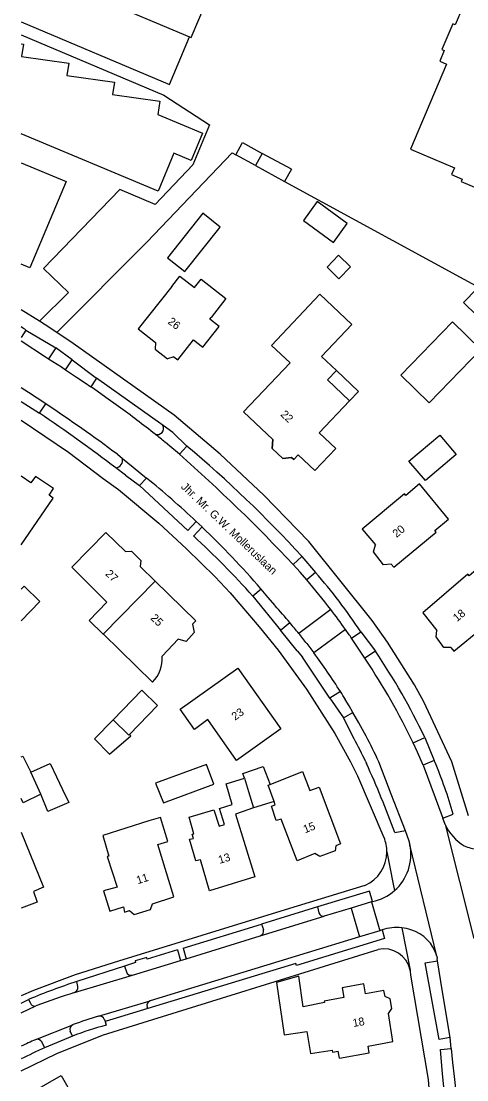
# Model space of a CAD drawing. Extents: x 194485 to 197793, y 468269 to 470822.
# Drawn here: x 194485.4 to 194552.2, y 470202.3 to 470361 of the extents above; entities that cross this region are included whole.
import ezdxf

# ---------------------------------------------------------------- set-up
doc = ezdxf.new("R2010")
doc.units = 0
for name, color, linetype in [('BGT grensvlak gebouwinstallatie plus 1', 7, 'Continuous'), ('BGT grensvlak onbegroeid terreindeel', 7, 'Continuous'), ('BGT grensvlak overig bouwwerk', 7, 'Continuous'), ('BGT grensvlak pand op maaiveld', 7, 'Continuous'), ('BGT grensvlak pand op maaiveld LR', 7, 'Continuous'), ('BGT grensvlak wegdeel', 7, 'Continuous'), ('BGT tekst huisnummerreeks', 7, 'Continuous'), ('BGT tekst openbare ruimte label weg', 7, 'Continuous'), ('GEM grensvlak beperking object', 7, 'Continuous')]:
    doc.layers.add(name, color=color, linetype=linetype)

msp = doc.modelspace()

# ---------------------------------------------------------------- linework, layer by layer
at = {"layer": 'BGT grensvlak gebouwinstallatie plus 1'}
msp.add_line((194520.54, 470339.4), (194517.6, 470341), dxfattribs=at)
for points in [[(194517.6, 470341), (194518.6, 470342.84), (194521.54, 470341.21)], [(194527.74, 470331.17), (194532.24, 470327.87), (194534.3, 470330.7), (194529.8, 470333.99), (194527.74, 470331.17)], [(194558.86, 470318.1), (194553.75, 470320.91), (194551.74, 470318.83), (194555.79, 470314.92)], [(194532.69, 470308.64), (194535.99, 470305.5), (194534.66, 470304.11)], [(194499.19, 470256.28), (194496.43, 470253.44), (194498.66, 470251.12), (194501.85, 470253.88), (194501.65, 470254.07)]]:
    msp.add_lwpolyline(points, dxfattribs=at)
at = {"layer": 'BGT grensvlak onbegroeid terreindeel'}
for points in [[(194485.41, 470360.93), (194507.65, 470351.54), (194510.67, 470358.68)], [(194485.41, 470358.98), (194506.79, 470349.95), (194513.67, 470345.49), (194511.17, 470339.51), (194505.51, 470333.57), (194500.21, 470335.79), (194488.75, 470323.97), (194492.49, 470320.35), (194488.18, 470316.04)], [(194485.41, 470339.81), (194492.14, 470336.99), (194486.73, 470324.06), (194485.41, 470324.62)], [(194490.75, 470314.36), (194504.26, 470327.9), (194517.03, 470341.31), (194517.6, 470341)], [(194524.92, 470336.98), (194557.37, 470319.3), (194558.33, 470321.04)]]:
    msp.add_lwpolyline(points, dxfattribs=at)
at = {"layer": 'BGT grensvlak overig bouwwerk'}
msp.add_lwpolyline([(194550.07, 470315.94), (194542.33, 470307.97), (194546.6, 470303.83), (194554.34, 470311.79), (194550.07, 470315.94)], dxfattribs=at)
at = {"layer": 'BGT grensvlak pand op maaiveld'}
for p, q in [((194486.27, 470368.98), (194510.67, 470358.68)), ((194521.54, 470341.21), (194520.54, 470339.4)), ((194525.93, 470338.83), (194521.54, 470341.21)), ((194520.54, 470339.4), (194524.92, 470336.98)), ((194525.93, 470338.83), (194524.92, 470336.98)), ((194507.99, 470321.24), (194509.22, 470322.82)), ((194509.22, 470322.82), (194511.41, 470321.1)), ((194511.41, 470321.1), (194512.39, 470322.36)), ((194512.39, 470322.36), (194516.12, 470319.45)), ((194507.99, 470321.24), (194502.94, 470314.89)), ((194516.12, 470319.45), (194513.91, 470316.61)), ((194502.94, 470314.89), (194505.54, 470312.86)), ((194505.54, 470312.86), (194505.49, 470311.88)), ((194505.49, 470311.88), (194507.34, 470310.43)), ((194508.28, 470310.72), (194507.34, 470310.43)), ((194497.72, 470269.14), (194497.75, 470269.12)), ((194497.75, 470269.12), (194505.12, 470261.91)), ((194518.66, 470248.25), (194521.7, 470249.29)), ((194521.7, 470249.29), (194522.77, 470246.6)), ((194490.73, 470247.72), (194491.63, 470245.82)), ((194518.88, 470247.54), (194518.66, 470248.25)), ((194523.33, 470244.02), (194520.27, 470243.06)), ((194533.15, 470205.55), (194532.97, 470206.58))]:
    msp.add_line(p, q, dxfattribs=at)
for points in [[(194510.67, 470358.68), (194510.9, 470358.59), (194514.35, 470366.76)], [(194551.64, 470363.2), (194550.49, 470360.49), (194550.12, 470360.65), (194548.48, 470356.78), (194548.86, 470356.62), (194548.18, 470355.02), (194549.19, 470354.59), (194543.8, 470341.87), (194550.39, 470339.05), (194549.96, 470338.04), (194551.56, 470337.35), (194551.4, 470336.98), (194555.27, 470335.34), (194555.43, 470335.72), (194558.14, 470334.57), (194557.98, 470334.19), (194561.85, 470332.55), (194562.01, 470332.93), (194563.6, 470332.25)], [(194485.41, 470357.66), (194485.75, 470357.61), (194485.48, 470355.74), (194492.55, 470354.76), (194492.28, 470352.89), (194499.39, 470351.89), (194499.12, 470350.03), (194506.2, 470349.04), (194505.92, 470347.06), (194512.61, 470344.25), (194510.9, 470340.17), (194508.3, 470341.23), (194505.94, 470335.55), (194485.41, 470344.15)], [(194507.36, 470325.57), (194509.94, 470323.51), (194515.25, 470330.17), (194512.67, 470332.23), (194507.36, 470325.57)], [(194533.02, 470325.93), (194531.28, 470324.14), (194533.07, 470322.4), (194534.81, 470324.19), (194533.02, 470325.93)], [(194532.69, 470308.64), (194530.43, 470310.78), (194534.98, 470315.57), (194530.21, 470320.08), (194522.96, 470312.42), (194525.73, 470309.79), (194518.75, 470302.48), (194523.14, 470298.29)], [(194508.28, 470310.72), (194508.88, 470310.25), (194511.27, 470313.27), (194512.65, 470312.18), (194515.09, 470315.27), (194513.71, 470316.37), (194513.91, 470316.61)], [(194532.69, 470308.64), (194531.36, 470307.24), (194534.66, 470304.11)], [(194534.66, 470304.11), (194530.11, 470299.33), (194532.6, 470296.96), (194529.43, 470293.64), (194526.95, 470296), (194526.28, 470295.3), (194525.96, 470295.6)], [(194546.02, 470292.16), (194543.56, 470295.07), (194548.17, 470298.95), (194550.62, 470296.04), (194546.02, 470292.16)], [(194525.96, 470295.6), (194524.64, 470295.46), (194523.85, 470296.21), (194523.06, 470296.97), (194523.14, 470298.29)], [(194485.41, 470282.52), (194490.21, 470289.49), (194489.6, 470289.95), (194490.27, 470290.98), (194487.57, 470292.78), (194486.86, 470291.81), (194485.41, 470292.8)], [(194540.91, 470279.62), (194541.31, 470279.15), (194547.65, 470284.42), (194547.44, 470284.67), (194549.49, 470286.38), (194545.15, 470291.64), (194543.1, 470289.93), (194542.89, 470290.17), (194536.56, 470284.89), (194538.53, 470282.51)], [(194498.28, 470273.9), (194493.01, 470279.15), (194498.1, 470284.38)], [(194498.1, 470284.38), (194501.06, 470281.53), (194501.97, 470281.55), (194503.35, 470280.18), (194503.26, 470279.29), (194505.53, 470277.08)], [(194540.91, 470279.62), (194539.76, 470279.53), (194538.24, 470281.47), (194538.53, 470282.51)], [(194549.82, 470267.14), (194550.3, 470266.55), (194554.46, 470269.95), (194555.5, 470269.47), (194557.04, 470270.73), (194556.78, 470271.84), (194557.24, 470272.22), (194557.04, 470272.47), (194559.75, 470274.69), (194555.26, 470280.13), (194552.61, 470277.85), (194552.39, 470278.1), (194545.63, 470272.31), (194547.76, 470269.68)], [(194485.41, 470275.87), (194485.86, 470276.33), (194488.2, 470274.02), (194485.41, 470271.14)], [(194505.53, 470277.08), (194511.62, 470271.14), (194511.1, 470270.6), (194511.35, 470269.36), (194510.17, 470268.04), (194508.96, 470268.36), (194506.56, 470265.81)], [(194498.28, 470273.9), (194495.62, 470271.18), (194497.72, 470269.14)], [(194549.82, 470267.14), (194548.78, 470267.12), (194547.62, 470268.72), (194547.76, 470269.68)], [(194517.69, 470250.2), (194513.38, 470256.32), (194511.38, 470254.82), (194509.24, 470257.88), (194517.89, 470264.02), (194524.36, 470254.92), (194517.69, 470250.2)], [(194501.65, 470254.07), (194505.87, 470258.43), (194503.49, 470260.73), (194499.19, 470256.28)], [(194499.19, 470256.28), (194501.56, 470253.98), (194501.65, 470254.07)], [(194485.41, 470250.71), (194485.67, 470250.83), (194486.86, 470248.41)], [(194486.86, 470248.41), (194489.76, 470249.74), (194490.73, 470247.72)], [(194514.31, 470246.63), (194513.19, 470249.58), (194505.58, 470246.77), (194506.74, 470243.83), (194514.31, 470246.63)], [(194522.77, 470246.6), (194527.58, 470248.52), (194528.72, 470245.66), (194530.12, 470246.16), (194533.31, 470237.68)], [(194520.27, 470243.06), (194517.57, 470242.12), (194520.43, 470232.72), (194513.64, 470230.64), (194512.28, 470235.3), (194511.61, 470235.13), (194510.64, 470238.36), (194511.27, 470238.49), (194511.04, 470239.15), (194511.3, 470239.2), (194510.58, 470241.67), (194514.3, 470242.78), (194515.12, 470240.34), (194515.89, 470240.59), (194515.16, 470242.99), (194517.07, 470243.59), (194516.16, 470246.67), (194518.88, 470247.54)], [(194488.37, 470245.15), (194485.71, 470243.84), (194485.41, 470244.48)], [(194491.63, 470245.82), (194492.54, 470243.86), (194489.43, 470242.55), (194488.37, 470245.15)], [(194533.31, 470237.68), (194532.62, 470237.36), (194532.48, 470236.61), (194530.2, 470235.77), (194529.45, 470236.24), (194526.8, 470235.14), (194524.42, 470241.39), (194523.66, 470241.17), (194522.95, 470243.34), (194523.51, 470243.53), (194523.33, 470244.02)], [(194505.92, 470237.6), (194507.4, 470238.04), (194506.33, 470241.64), (194504.54, 470241.12)], [(194504.54, 470241.12), (194497.64, 470238.94), (194498.57, 470235.85), (194498.31, 470235.78), (194499.81, 470231.16), (194497.76, 470230.63), (194498.73, 470227.6), (194500.74, 470228.22), (194500.93, 470227.44), (194501.64, 470227.66), (194502.35, 470227.09), (194504.83, 470227.83), (194505.09, 470228.67), (194508.28, 470229.75), (194505.92, 470237.6)], [(194485.41, 470239.44), (194488.74, 470231.16), (194487.24, 470230.53), (194487.82, 470228.91), (194485.41, 470228.02)], [(194527.68, 470213.23), (194527.04, 470217.83), (194523.71, 470216.89), (194524.83, 470209.05), (194528.27, 470209.54)], [(194537.43, 470207.36), (194541.13, 470208.02), (194540.49, 470212.26), (194541.02, 470212.99), (194540.77, 470214.46), (194540, 470214.8), (194539.78, 470215.69), (194537.06, 470215.21), (194536.8, 470216.67), (194533.55, 470216.1), (194533.81, 470214.64), (194530.84, 470214.11), (194530.92, 470213.88), (194527.68, 470213.23)], [(194528.27, 470209.54), (194528.8, 470206.22), (194532.07, 470206.74), (194532.12, 470206.43), (194532.97, 470206.58)], [(194533.15, 470205.55), (194537.61, 470206.33), (194537.43, 470207.36)], [(194485.41, 470199.49), (194491.4, 470202.92), (194494.46, 470197.58), (194495.57, 470198.23), (194498.08, 470193.97), (194496.69, 470193.16)]]:
    msp.add_lwpolyline(points, dxfattribs=at)
msp.add_arc((194501.47, 470265.48), 5.11, 315.6191, 3.6495, dxfattribs=at)
at = {"layer": 'BGT grensvlak pand op maaiveld LR'}
for p, q in [((194497.72, 470269.14), (194505.53, 470277.08)), ((194488.37, 470245.15), (194486.86, 470248.41)), ((194518.88, 470247.54), (194519.5, 470245.55)), ((194522.43, 470246.46), (194522.77, 470246.6)), ((194523.33, 470244.02), (194522.43, 470246.46)), ((194519.5, 470245.55), (194520.27, 470243.06))]:
    msp.add_line(p, q, dxfattribs=at)
at = {"layer": 'BGT grensvlak wegdeel'}
for p, q in [((194488.18, 470316.04), (194485.41, 470317.76)), ((194486.13, 470314.72), (194485.41, 470313.6)), ((194486.13, 470314.72), (194490.6, 470312.05)), ((194490.6, 470312.05), (194489.53, 470310.42)), ((194493.07, 470310.27), (194490.6, 470312.05)), ((194492.07, 470308.78), (194493.07, 470310.27)), ((194493.07, 470310.27), (194496.7, 470307.51)), ((194496.7, 470307.51), (194495.86, 470306.22)), ((194506.68, 470300.42), (194496.7, 470307.51)), ((194485.41, 470304.03), (194488.16, 470302.26)), ((194488.16, 470302.26), (194489.09, 470303.65)), ((194508.14, 470299.38), (194506.68, 470300.42)), ((194508.14, 470299.38), (194510.25, 470297.33)), ((194510.25, 470297.33), (194509.14, 470296.09)), ((194499.84, 470296.1), (194500.59, 470295.48)), ((194500.59, 470295.48), (194502.21, 470294.15)), ((194501.07, 470292.94), (194499.62, 470294.04)), ((194502.21, 470294.15), (194504.2, 470292.52)), ((194501.07, 470292.94), (194503.17, 470291.39)), ((194503.17, 470291.39), (194504.2, 470292.52)), ((194511.66, 470286.02), (194512.53, 470285.19)), ((194511.24, 470283.84), (194512.53, 470285.19)), ((194526.19, 470279.55), (194527.52, 470280.78)), ((194527.52, 470280.78), (194529.54, 470278.38)), ((194529.54, 470278.38), (194528.24, 470277.26)), ((194521.38, 470275.89), (194520.14, 470274.83)), ((194520.14, 470274.83), (194524.3, 470269.74)), ((194531.84, 470272.82), (194527.04, 470269.23)), ((194524.3, 470269.74), (194525.7, 470270.85)), ((194526.82, 470266.6), (194524.3, 470269.74)), ((194534.04, 470269.84), (194529.3, 470266.3)), ((194534.95, 470268.52), (194536.35, 470269.47)), ((194536.35, 470269.47), (194538.53, 470266.58)), ((194528.25, 470267.7), (194529.3, 470266.3)), ((194526.82, 470266.6), (194527.61, 470265.67)), ((194531.68, 470259.51), (194527.61, 470265.67)), ((194538.53, 470266.58), (194536.94, 470265.5)), ((194537.03, 470265.36), (194536.94, 470265.5)), ((194533.29, 470260.5), (194531.68, 470259.51)), ((194531.68, 470259.51), (194533.77, 470256.57)), ((194533.77, 470256.57), (194535.17, 470257.39)), ((194535.35, 470253.45), (194533.77, 470256.57)), ((194544.2, 470252.81), (194545.93, 470253.64)), ((194545.93, 470253.64), (194547.34, 470250.2)), ((194537.1, 470250), (194537.2, 470249.72)), ((194547.34, 470250.2), (194545.71, 470249.49)), ((194545.71, 470249.49), (194548.63, 470241.54)), ((194547.43, 470250), (194547.34, 470250.2)), ((194548.63, 470241.54), (194550.21, 470242.12)), ((194548.98, 470240.56), (194548.63, 470241.54)), ((194548.98, 470240.56), (194553.3, 470223.49)), ((194543.03, 470239.65), (194541.45, 470239.35)), ((194543.59, 470238.09), (194543.03, 470239.65)), ((194547.72, 470220.82), (194543.72, 470237.54)), ((194540.24, 470236.48), (194541.21, 470231.61)), ((194541.21, 470231.61), (194541.39, 470230.67)), ((194537.93, 470228.97), (194534.91, 470228.05)), ((194538.11, 470229.02), (194537.93, 470228.97)), ((194537.93, 470228.97), (194539.18, 470224.65)), ((194529.84, 470228.22), (194521.47, 470225.65)), ((194529.84, 470228.22), (194530.07, 470227.34)), ((194534.91, 470228.05), (194530.86, 470226.82)), ((194534.91, 470228.05), (194536.16, 470223.73)), ((194509.71, 470222.04), (194521.47, 470225.65)), ((194521.27, 470223.89), (194530.86, 470226.82)), ((194521.47, 470225.65), (194521.74, 470224.82)), ((194510.15, 470220.46), (194521.27, 470223.89)), ((194539.18, 470224.65), (194536.16, 470223.73)), ((194539.55, 470224.76), (194539.18, 470224.65)), ((194542.49, 470225.1), (194543.75, 470218.76)), ((194536.16, 470223.73), (194504.74, 470214.14)), ((194508.85, 470221.77), (194509.29, 470220.2)), ((194509.71, 470222.04), (194510.15, 470220.46)), ((194547.72, 470220.82), (194547.8, 470220.49)), ((194500.92, 470219.33), (194493.75, 470217.02)), ((194500.92, 470219.33), (194501.19, 470218.51)), ((194502.12, 470217.99), (194509.29, 470220.2)), ((194509.29, 470220.2), (194510.15, 470220.46)), ((194547.86, 470220.13), (194547.8, 470220.49)), ((194493.41, 470215.38), (194502.12, 470217.99)), ((194493.9, 470216.29), (194493.75, 470217.02)), ((194485.41, 470213.81), (194486.53, 470214.33)), ((194485.41, 470212.32), (194487.62, 470213.38)), ((194486.53, 470214.33), (194486.81, 470213.81)), ((194487.76, 470213.44), (194487.62, 470213.38)), ((194497, 470211.83), (194504.74, 470214.14)), ((194504.4, 470212.98), (194497.99, 470211.06)), ((194504.4, 470212.98), (194504.31, 470213.26)), ((194497.91, 470211.32), (194497.99, 470211.06)), ((194487.59, 470208.32), (194493.14, 470210.54)), ((194493.12, 470208.86), (194492.76, 470209.59)), ((194493.21, 470210.57), (194493.14, 470210.54)), ((194497.99, 470211.06), (194498.15, 470210.49)), ((194487.59, 470208.32), (194487.55, 470208.31)), ((194493.12, 470208.86), (194488.89, 470207.08)), ((194549.89, 470206.99), (194549.74, 470208.62)), ((194488.53, 470207.93), (194488.89, 470207.08))]:
    msp.add_line(p, q, dxfattribs=at)
for points in [[(194490.75, 470314.36), (194489.02, 470315.51), (194488.18, 470316.04)], [(194552.5, 470241.9), (194549.98, 470250), (194545.77, 470258.98), (194544.42, 470261.5), (194540.37, 470267.9), (194538.06, 470271.19), (194528.56, 470283.04), (194521.79, 470289.95), (194515.24, 470296.12), (194508.37, 470301.96), (194493.23, 470312.72), (194490.75, 470314.36)], [(194485.41, 470313.12), (194489.08, 470310.7), (194489.53, 470310.42)], [(194489.53, 470310.42), (194491.44, 470309.19), (194492.07, 470308.78)], [(194492.07, 470308.78), (194493.73, 470307.68), (194494.99, 470306.82), (194495.86, 470306.22)], [(194489.09, 470303.65), (194486.52, 470305.34), (194485.41, 470306.05)], [(194500, 470303.28), (194498.13, 470304.63), (194496.24, 470305.96), (194495.86, 470306.22)], [(194485.41, 470301.19), (194492.5, 470296.42), (194497.72, 470292.47), (194500, 470290.79), (194506.06, 470285.74), (194510.2, 470281.91), (194514.52, 470277.71), (194516.76, 470275.3), (194521.1, 470270.2), (194523.93, 470266.7), (194528.21, 470260.88), (194532.45, 470254.21), (194534.79, 470250), (194535.86, 470247.89), (194539.82, 470238.61)], [(194509.14, 470296.09), (194507.72, 470297.33), (194506.98, 470297.93)], [(194503.17, 470291.39), (194510.4, 470284.67), (194511.66, 470286.02)], [(194528.24, 470277.26), (194527.23, 470278.41), (194526.19, 470279.55)], [(194523.48, 470273.4), (194522.41, 470274.68), (194521.38, 470275.89)], [(194536.94, 470265.5), (194535.96, 470267.02), (194534.95, 470268.52)], [(194535.17, 470257.39), (194534.61, 470258.35), (194534.02, 470259.31)], [(194536.9, 470254.28), (194536.05, 470255.84), (194535.17, 470257.39)], [(194545.71, 470249.49), (194544.86, 470251.41), (194544.2, 470252.81)], [(194543.03, 470239.65), (194540.88, 470245.11), (194539.04, 470250), (194538.81, 470250.49)], [(194536.96, 470231.42), (194525.02, 470227.76), (194500, 470220.11), (194493.52, 470218.05), (194487.28, 470215.68), (194485.41, 470214.88)], [(194538.11, 470229.02), (194537.65, 470230.57), (194529.84, 470228.22)], [(194539.55, 470224.76), (194539.9, 470223.47), (194526.69, 470219.46), (194526.61, 470219.74), (194504.4, 470212.98)], [(194485.41, 470203.66), (194490.77, 470206.25), (194497.61, 470208.97), (194500, 470209.74), (194538.94, 470221.84)], [(194508.85, 470221.77), (194504.3, 470220.38), (194504.24, 470220.65), (194502.49, 470220.14), (194502.55, 470219.87), (194500.92, 470219.33)], [(194549.74, 470208.62), (194548.08, 470208.36), (194545.99, 470219.84), (194547.86, 470220.13)], [(194549.74, 470208.62), (194548.59, 470215.49), (194547.86, 470220.13)], [(194538.71, 470115.06), (194541.76, 470132.92), (194544.49, 470148.78), (194546.12, 470161.52), (194547.24, 470174.3), (194547.43, 470181.27), (194547.35, 470188.24), (194547.04, 470195.29), (194546.51, 470202.32), (194543.84, 470218.01)], [(194550.93, 470197.44), (194549.18, 470197.23), (194548.61, 470203.2), (194548.29, 470206.84), (194549.89, 470206.99)], [(194549.89, 470206.99), (194550.09, 470204.88), (194550.32, 470202.78), (194550.93, 470197.44)]]:
    msp.add_lwpolyline(points, dxfattribs=at)
for centre, radius, start, end in [((194390.43, 470166.64), 176.31, 57.1283, 57.4052), ((194348.17, 470091.58), 254.62, 53.4393, 56.3959), ((194386.53, 470147.95), 192.36, 51.7873, 53.851), ((194337.32, 470079.91), 268.69, 52.8396, 55.8481), ((194505.8, 470300.01), 0.967, 253.1274, 24.9588), ((194387.71, 470149.44), 190.46, 51.2291, 51.7883), ((194391.46, 470156.07), 184.57, 42.5058, 49.9368), ((194499.42, 470295.22), 1.2, 279.911, 12.7454), ((194346.1, 470110.87), 246.76, 43.126, 48.6443), ((194419.29, 470187.57), 135, 46.8238, 51.0254), ((194419.36, 470187.72), 134.84, 40.8389, 46.2944), ((194432.15, 470196.84), 117.58, 41.5502, 47.7271), ((194468.53, 470224.65), 81.29, 33.4624, 41.3746), ((194454.11, 470213.34), 97.88, 37.422, 40.7706), ((194452.62, 470209.26), 95.57, 40.1211, 42.1454), ((194453.93, 470213.2), 98.1, 35.2589, 37.4233), ((194449.88, 470207.04), 99.1, 38.8666, 40.0808), ((194456.95, 470212.65), 90.08, 37.6718, 38.9158), ((194466.61, 470221.96), 82.69, 34.2636, 35.3752), ((194453.18, 470209.78), 94.82, 32.3375, 36.5915), ((194455.7, 470210.5), 98.1, 25.5518, 34), ((194456.34, 470210.93), 99.25, 25.4872, 34.0998), ((194454.24, 470210.43), 93.58, 31.4959, 32.3493), ((194453.24, 470209.78), 94.76, 25.4407, 28.0038), ((194453.39, 470209.85), 92.83, 25.6239, 28.01), ((194391.09, 470183.74), 160.32, 20.2987, 24.3048), ((194484.88, 470223.47), 67.94, 15.9305, 22.9853), ((194555.51, 470243.57), 7.18, 204.7827, 239.1897), ((194534.68, 470236.49), 5.57, 359.8974, 22.4017), ((194536.57, 470236.13), 7.29, 311.461, 11.0991), ((194537.2, 470236.27), 6.64, 10.9987, 15.8985), ((194554.16, 470242.35), 5.47, 244.7396, 267.3951), ((194534.69, 470236.5), 5.56, 294.1227, 359.8829), ((194536.61, 470236.1), 7.24, 281.9855, 311.3818), ((194530.73, 470227.48), 0.671, 191.5502, 281.4386), ((194521.02, 470224.6), 0.755, 289.1745, 16.7139), ((194541.75, 470218.64), 6.51, 83.4637, 109.7844), ((194541.75, 470218.63), 6.51, 71.106, 83.4914), ((194542.19, 470219.31), 5.74, 15.3069, 73.0409), ((194539.8, 470217.89), 4.04, 12.3382, 102.2082), ((194501.91, 470218.72), 0.758, 196.7731, 285.6526), ((194539.89, 470217.91), 3.95, 1.5796, 12.4229), ((194518.55, 470139.5), 81.39, 107.7428, 113.1655), ((194493.17, 470216.09), 0.752, 288.1695, 15.4907), ((194519.75, 470129.16), 90.15, 106.9877, 110.7859), ((194487.42, 470213.97), 0.627, 195.1304, 288.7689), ((194504.98, 470213.48), 0.704, 109.8362, 197.8721), ((194511.45, 470161.79), 52.08, 106.1116, 110.5042), ((194497.2, 470211.11), 0.74, 15.8805, 105.6372), ((194493.45, 470209.87), 0.745, 114.9164, 201.9579), ((194512.7, 470156.9), 55.53, 105.193, 110.6567), ((194519.82, 470134.15), 80.87, 113.521, 115.1805), ((194487.85, 470207.61), 0.756, 24.8374, 110.1895), ((194530.03, 470116.22), 99.74, 114.3579, 116.5729)]:
    msp.add_arc(centre, radius, start, end, dxfattribs=at)
at = {"layer": 'GEM grensvlak beperking object'}
for points in [[(194485.41, 470357.66), (194485.75, 470357.61), (194485.48, 470355.74), (194492.55, 470354.76), (194492.28, 470352.89), (194499.39, 470351.89), (194499.12, 470350.03), (194506.2, 470349.04), (194505.92, 470347.06), (194512.61, 470344.25), (194510.9, 470340.17), (194508.3, 470341.23), (194505.94, 470335.55), (194485.41, 470344.15)], [(194522.96, 470312.42), (194525.73, 470309.79), (194518.75, 470302.48), (194523.14, 470298.29), (194523.06, 470296.97), (194524.64, 470295.46), (194525.96, 470295.6), (194526.28, 470295.3), (194526.95, 470296), (194529.43, 470293.64), (194532.6, 470296.96), (194530.11, 470299.33), (194534.66, 470304.11), (194531.36, 470307.24), (194532.69, 470308.64), (194530.43, 470310.78), (194534.98, 470315.57), (194530.21, 470320.08), (194522.96, 470312.42)]]:
    msp.add_lwpolyline(points, dxfattribs=at)

# ---------------------------------------------------------------- texts
at = {"layer": 'BGT tekst huisnummerreeks'}
for s, rotation, p in [('26', 322, (194507.3, 470315.8)), ('22', 316.4, (194524.22, 470301.96)), ('20', 39.6, (194541.71, 470283.54)), ('27', 315.5, (194497.95, 470278.07)), ('25', 315.7, (194504.72, 470271.44)), ('18', 39, (194550.76, 470270.92)), ('23', 35.4, (194517.49, 470256.14)), ('15', 21.3, (194527.98, 470239.25)), ('13', 17, (194515.18, 470234.67)), ('11', 17.5, (194502.9, 470231.62)), ('18', 10, (194535.23, 470210.21))]:
    msp.add_text(s, height=1.2, rotation=rotation, dxfattribs=at).set_placement(p)
at = {"layer": 'BGT tekst openbare ruimte label weg'}
msp.add_text('Jhr. Mr. G.W. Molleruslaan', height=1.2, rotation=316.4, dxfattribs=at).set_placement((194509.29, 470291.12))

doc.saveas('drawing.dxf')
